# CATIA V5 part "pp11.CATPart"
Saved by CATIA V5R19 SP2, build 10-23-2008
Part number: pp11
Bounding box of the stored display mesh (mm): x -18 to 18, y -108.398 to 108.398, z -68 to -34.146
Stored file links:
  D:\thinkmotion-MPB\Dropbox\Pack 1 sylvain\jlicbarski\thk2\pp11.CATPart
  D:\thinkmotion-MPB\Dropbox\Pack 1 sylvain\jlicbarski\thk2\Brasmeca.CATProduct
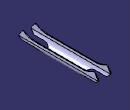
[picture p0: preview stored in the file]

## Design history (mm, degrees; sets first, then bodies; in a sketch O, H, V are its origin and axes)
External parameters (linked from other documents)
  External.Length.1 = 16 mm
  External.Length.2 = 18 mm
  External.Length.4 = 32 mm
  External.Length.3 = 36 mm
  External.Length.5 = 17.604 mm
AxisSystem1: origin (0, 0, 0), X (1, 0, 0), Y (0, 1, 0), Z (0, 0, 1)
Set1
  Plane1: linked copy from another document
  Line1: linked copy from another document
  Line2: linked copy from another document
Body1 (main body)
  Sketch1 on Plane1, origin (0, -110, 0), H (-1, 0, 0), V (0, 0, 1)
    arc A1 centre (0, -50) radius 16 from (-16, -50) to (16, -50) ccw
    arc A2 centre (0, -50) radius 18 from (-18, -50) to (18, -50) ccw
    reference projected point E1 (0, -50) from Line2
    reference projected point E2 (0, -50) from Line2
    line L1 (18, -50) -> (18, -32.396)
    line L2 (16, -50) -> (16, -32.396)
    line L3 (18, -32.396) -> (16, -32.396)
    line L4 (-16, -50) -> (-16, -32.396)
    line L5 (-18, -50) -> (-18, -32.396)
    line L6 (-16, -32.396) -> (-18, -32.396)
    radius A2 = 18 {= External.Length.3 /2}
    radius A1 = 16 {= External.Length.4 /2}
    distance A1 E1 = 16 {= External.Length.1}
    distance A2 E2 = 18 {= External.Length.2}
    length L1 = 17.604 {= External.Length.5}
  Pad1: profile Sketch1, direction (0, 1, 0), length 220
  Sketch2 on face of Pad1 from Sketch1.L1, origin (-18, 0, 0), H (0, -1, 0), V (0, 0, 1)
    line L1 (94.8168, -34.6001) -> (93.0302, -35.6116)
    arc A1 centre (96.9003, -39.0985) radius 4.9575 from (101.0444, -36.3776) to (94.8168, -34.6001) ccw
    arc A2 centre (104.0516, -48.9972) radius 4.3474 from (107.1732, -45.9714) to (107.5433, -51.5872) cw
    reference projected line E1 (110, -32.396) -> (-110, -32.396) from edge [face of Pad1 from Sketch1.L3 | face of Pad1 from Sketch1.L1]
    reference projected line E2 (110, -50) -> (110, -32.396) from edge [start face of Pad1 | face of Pad1 from Sketch1.L1]
    line L2 (107.1732, -45.9714) -> (101.0444, -36.3776)
    line L3 (55.3574, -63.0197) -> (46.7354, -67.901)
    line L4 (46.7354, -67.901) -> (137.0088, -69.761)
    line L5 (-56.4691, -62.3903) -> (-46.7354, -67.901)
    arc A3 centre (-98.5112, -52.8006) radius 5.9984 from (-101.4916, -58.0062) to (-98.5112, -58.799) ccw
    arc A4 centre (-104.0516, -48.9972) radius 4.3474 from (-107.1732, -45.9714) to (-107.5433, -51.5872) ccw
    line L6 (-107.1732, -45.9714) -> (-101.0444, -36.3776)
    arc A5 centre (-96.9003, -39.0985) radius 4.9575 from (-101.0444, -36.3776) to (-94.8168, -34.6001) cw
    line L7 (-94.8168, -34.6001) -> (-93.4277, -35.3865)
    line L8 (-64.3365, -43.05) -> (-55.4929, -43.05)
    line L9 (55.4929, -43.05) -> (-55.4929, -43.05)
    arc A6 centre (64.7933, 14.2639) radius 57.3139 from (93.0302, -35.6116) to (64.7933, -43.05) cw
    arc A7 centre (-64.3365, 15.9981) radius 59.0481 from (-93.4277, -35.3865) to (-64.3365, -43.05) ccw
    line L10 (137.0088, -69.761) -> (112.7194, -6.0637)
    line L11 (112.7194, -6.0637) -> (-128.2581, -28.2281)
    line L12 (-128.2581, -28.2281) -> (-142.8759, -74.2786)
    line L13 (-142.8759, -74.2786) -> (-36.7083, -85.4685)
    line L14 (-36.7083, -85.4685) -> (1.6481, -79.7761)
    arc A8 centre (71.3795, -91.32) radius 32.521 from (71.3795, -58.799) to (55.3574, -63.0197) ccw
    arc A9 centre (-70.102, -86.4705) radius 27.6715 from (-70.102, -58.799) to (-56.4691, -62.3903) cw
    line L15 (-46.7354, -67.901) -> (1.6481, -79.7761)
    line L16 (64.7933, -43.05) -> (55.4929, -43.05)
    line L17 (-70.102, -58.799) -> (-98.5112, -58.799)
    line L18 (-101.4916, -58.0062) -> (-107.5433, -51.5872)
    line L19 (71.3795, -58.799) -> (97.6502, -58.799)
    arc A10 centre (97.6502, -51.63) radius 7.169 from (102.8665, -56.5478) to (97.6502, -58.799) cw
    line L20 (107.5433, -51.5872) -> (102.8665, -56.5478)
    distance A1 E1 = 1.745
    distance A2 E2 = 1.601
  Pocket1: profile Sketch2, direction (1, 0, 0), length 220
